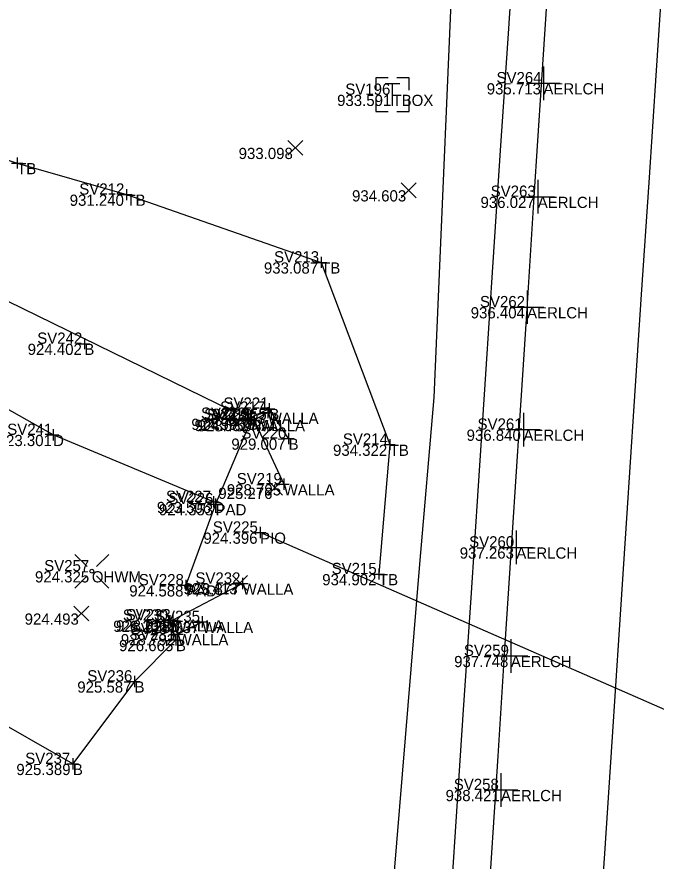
# Model space of a CAD drawing. Extents: x 1988835 to 1989144, y 657973 to 659339.
# Drawn here: x 1988936.8 to 1988993.8, y 658662.1 to 658737.4 of the extents above; entities that cross this region are included whole.
import ezdxf

# ---------------------------------------------------------------- set-up
doc = ezdxf.new("R2010")
doc.units = 0
for name, color, linetype in [('BR_X_SV_Abut', 7, 'Continuous'), ('BR_X_SV_Abut_Text', 7, 'Continuous'), ('DR_X_Culvert', 7, 'Continuous'), ('DR_X_Ditch', 7, 'Continuous'), ('DR_X_Elev_Flow', 7, 'Continuous'), ('PM_X_CL_Pass_Proh_Rt', 7, 'Continuous'), ('PV_X_EOP', 7, 'Continuous'), ('PV_X_Shoulder_Aggregate', 7, 'Continuous'), ('RD_X_Concrete_Pad', 7, 'Continuous'), ('SV_X_Break_Lines', 7, 'Continuous'), ('SV_X_Control_Cells_Found', 7, 'Continuous'), ('SV_X_LiDAR_Check_Spots', 7, 'Continuous'), ('SV_X_Random_Point', 7, 'Continuous'), ('SV_X_Shot_Marker', 7, 'Continuous'), ('SV_X_Text_Comment', 7, 'Continuous'), ('SV_X_Top_of_Bank', 7, 'Continuous'), ('UT_X_Telecom', 7, 'Continuous'), ('UT_X_Telecom_Cells', 7, 'Continuous')]:
    doc.layers.add(name, color=color, linetype=linetype)

msp = doc.modelspace()

# ---------------------------------------------------------------- linework, layer by layer
at = {"layer": 'BR_X_SV_Abut'}
for points in [[(1988959.153, 658702.097), (1988957.947, 658701.429), (1988960.579, 658695.713)], [(1988956.909, 658686.847), (1988950.685, 658683.575), (1988951.112, 658682.342), (1988953.32, 658683.43)]]:
    msp.add_lwpolyline(points, dxfattribs=at)
at = {"layer": 'DR_X_Culvert'}
msp.add_line((1989019.511, 658664.679), (1988958.476, 658691.4), dxfattribs=at)
at = {"layer": 'DR_X_Ditch'}
msp.add_lwpolyline([(1988954.33, 658694.137), (1988940.011, 658700.115), (1988927.983, 658706.906), (1988920.687, 658710.159)], dxfattribs=at)
at = {"layer": 'DR_X_Elev_Flow'}
for p, q in [((1988958.476, 658691.9), (1988958.476, 658690.9)), ((1988957.976, 658691.4), (1988958.976, 658691.4)), ((1988958.476, 658691.4), (1988958.476, 658691.4))]:
    msp.add_line(p, q, dxfattribs=at)
at = {"layer": 'PM_X_CL_Pass_Proh_Rt'}
msp.add_lwpolyline([(1988985.91, 658612.87), (1988986.569, 658622.848), (1988987.228, 658632.826), (1988987.887, 658642.804), (1988988.547, 658652.783), (1988989.206, 658662.761), (1988989.865, 658672.739), (1988990.524, 658682.717), (1988991.184, 658692.696), (1988991.843, 658702.674), (1988992.502, 658712.652), (1988993.161, 658722.63), (1988993.821, 658732.609), (1988994.48, 658742.587), (1988995.139, 658752.565), (1988995.798, 658762.543), (1988996.458, 658772.522), (1988997.117, 658782.5), (1988997.776, 658792.478), (1988998.435, 658802.456), (1988999.095, 658812.435), (1988999.754, 658822.413), (1989000.413, 658832.391), (1989001.072, 658842.369)], dxfattribs=at)
at = {"layer": 'PV_X_EOP'}
msp.add_lwpolyline([(1988990.638, 658841.098), (1988989.993, 658831.118), (1988989.347, 658821.139), (1988988.702, 658811.16), (1988988.057, 658801.181), (1988987.411, 658791.202), (1988986.766, 658781.223), (1988986.12, 658771.244), (1988985.475, 658761.264), (1988984.83, 658751.285), (1988984.184, 658741.306), (1988983.539, 658731.327), (1988982.893, 658721.348), (1988982.248, 658711.369), (1988981.602, 658701.389), (1988980.957, 658691.41), (1988980.312, 658681.431), (1988979.666, 658671.452), (1988979.021, 658661.473), (1988978.375, 658651.494), (1988977.73, 658641.515), (1988977.084, 658631.535), (1988976.439, 658621.556), (1988975.794, 658611.577)], dxfattribs=at)
at = {"layer": 'PV_X_Shoulder_Aggregate'}
msp.add_lwpolyline([(1988987.168, 658835.248), (1988986.507, 658825.269), (1988985.846, 658815.291), (1988985.185, 658805.313), (1988984.524, 658795.335), (1988983.863, 658785.357), (1988983.203, 658775.379), (1988982.542, 658765.401), (1988981.881, 658755.422), (1988981.22, 658745.444), (1988980.559, 658735.466), (1988979.898, 658725.488), (1988979.237, 658715.51), (1988978.577, 658705.532), (1988977.916, 658695.554), (1988977.255, 658685.575), (1988976.594, 658675.597), (1988975.933, 658665.619), (1988975.272, 658655.641), (1988974.612, 658645.663), (1988973.951, 658635.685), (1988973.29, 658625.707), (1988972.629, 658615.728)], dxfattribs=at)
at = {"layer": 'RD_X_Concrete_Pad'}
msp.add_lwpolyline([(1988957.682, 658701.45), (1988954.501, 658693.936), (1988951.864, 658686.696)], dxfattribs=at)
at = {"layer": 'SV_X_Break_Lines'}
for points in [[(1988961.012, 658699.789), (1988959.296, 658702.449), (1988957.403, 658701.554), (1988930.572, 658714.671)], [(1988942.8, 658708.246), (1988942.8, 658708.246)], [(1988950.438, 658683.541), (1988950.966, 658681.818), (1988947.272, 658678.12), (1988941.777, 658670.765), (1988909.757, 658689.092), (1988888.695, 658704.246)]]:
    msp.add_lwpolyline(points, dxfattribs=at)
at = {"layer": 'SV_X_Control_Cells_Found'}
for p, q in [((1988941.958, 658689.454), (1988943.051, 658688.36)), ((1988943.884, 658688.36), (1988944.976, 658689.454)), ((1988941.958, 658686.435), (1988943.051, 658687.529)), ((1988943.884, 658687.529), (1988944.976, 658686.435))]:
    msp.add_line(p, q, dxfattribs=at)
msp.add_circle((1988943.468, 658687.95), 0.17, dxfattribs=at)
at = {"layer": 'SV_X_LiDAR_Check_Spots'}
for p, q in [((1988983.736, 658732.986), (1988983.736, 658729.986)), ((1988982.236, 658731.486), (1988985.236, 658731.486)), ((1988983.736, 658731.486), (1988983.736, 658731.486)), ((1988983.233, 658722.855), (1988983.233, 658719.855)), ((1988981.733, 658721.355), (1988984.733, 658721.355)), ((1988983.233, 658721.355), (1988983.233, 658721.355)), ((1988982.286, 658713.006), (1988982.286, 658710.006)), ((1988980.786, 658711.506), (1988983.786, 658711.506)), ((1988982.286, 658711.506), (1988982.286, 658711.506)), ((1988981.953, 658702.083), (1988981.953, 658699.083)), ((1988980.453, 658700.583), (1988983.453, 658700.583)), ((1988981.953, 658700.583), (1988981.953, 658700.583)), ((1988981.325, 658691.573), (1988981.325, 658688.573)), ((1988979.825, 658690.073), (1988982.825, 658690.073)), ((1988981.325, 658690.073), (1988981.325, 658690.073)), ((1988980.837, 658681.892), (1988980.837, 658678.892)), ((1988979.337, 658680.392), (1988982.337, 658680.392)), ((1988980.837, 658680.392), (1988980.837, 658680.392)), ((1988979.955, 658669.937), (1988979.955, 658666.937)), ((1988978.455, 658668.437), (1988981.455, 658668.437)), ((1988979.955, 658668.437), (1988979.955, 658668.437))]:
    msp.add_line(p, q, dxfattribs=at)
at = {"layer": 'SV_X_Random_Point'}
for p, q in [((1988960.954, 658725.055), (1988962.287, 658726.39)), ((1988960.954, 658726.39), (1988962.287, 658725.055)), ((1988971.054, 658721.27), (1988972.387, 658722.605)), ((1988971.054, 658722.605), (1988972.387, 658721.27)), ((1988959.142, 658694.733), (1988960.475, 658696.068)), ((1988959.142, 658696.068), (1988960.475, 658694.733)), ((1988956.017, 658686.222), (1988957.35, 658687.557)), ((1988956.017, 658687.557), (1988957.35, 658686.222)), ((1988941.859, 658683.513), (1988943.192, 658684.848)), ((1988941.859, 658684.848), (1988943.192, 658683.513))]:
    msp.add_line(p, q, dxfattribs=at)
at = {"layer": 'SV_X_Shot_Marker'}
for p, q in [((1988936.302, 658724.364), (1988937.302, 658724.364)), ((1988936.802, 658724.864), (1988936.802, 658723.864)), ((1988936.802, 658724.364), (1988936.802, 658724.364)), ((1988946.553, 658722.048), (1988946.553, 658721.048)), ((1988946.053, 658721.548), (1988947.053, 658721.548)), ((1988946.553, 658721.548), (1988946.553, 658721.548)), ((1988963.916, 658716.002), (1988963.916, 658715.002)), ((1988963.416, 658715.502), (1988964.416, 658715.502)), ((1988963.916, 658715.502), (1988963.916, 658715.502)), ((1988942.8, 658708.746), (1988942.8, 658707.746)), ((1988942.3, 658708.246), (1988943.3, 658708.246)), ((1988942.8, 658708.246), (1988942.8, 658708.246)), ((1988958.796, 658702.449), (1988959.796, 658702.449)), ((1988959.153, 658702.597), (1988959.153, 658701.597)), ((1988959.296, 658702.949), (1988959.296, 658701.949)), ((1988959.296, 658702.449), (1988959.296, 658702.449)), ((1988957.403, 658702.054), (1988957.403, 658701.054)), ((1988957.682, 658701.95), (1988957.682, 658700.95)), ((1988957.947, 658701.929), (1988957.947, 658700.929)), ((1988958.653, 658702.097), (1988959.653, 658702.097)), ((1988959.153, 658702.097), (1988959.153, 658702.097)), ((1988956.903, 658701.554), (1988957.903, 658701.554)), ((1988957.182, 658701.45), (1988958.182, 658701.45)), ((1988957.403, 658701.554), (1988957.403, 658701.554)), ((1988957.447, 658701.429), (1988958.447, 658701.429)), ((1988957.682, 658701.45), (1988957.682, 658701.45)), ((1988957.947, 658701.429), (1988957.947, 658701.429)), ((1988939.511, 658700.115), (1988940.511, 658700.115)), ((1988940.011, 658700.615), (1988940.011, 658699.615)), ((1988940.011, 658700.115), (1988940.011, 658700.115)), ((1988961.012, 658700.289), (1988961.012, 658699.289)), ((1988960.512, 658699.789), (1988961.512, 658699.789)), ((1988961.012, 658699.789), (1988961.012, 658699.789)), ((1988970.033, 658699.743), (1988970.033, 658698.743)), ((1988969.533, 658699.243), (1988970.533, 658699.243)), ((1988970.033, 658699.243), (1988970.033, 658699.243)), ((1988960.079, 658695.713), (1988961.079, 658695.713)), ((1988960.579, 658696.213), (1988960.579, 658695.213)), ((1988960.579, 658695.713), (1988960.579, 658695.713)), ((1988953.83, 658694.137), (1988954.83, 658694.137)), ((1988954.33, 658694.637), (1988954.33, 658693.637)), ((1988954.33, 658694.137), (1988954.33, 658694.137)), ((1988954.501, 658694.436), (1988954.501, 658693.436)), ((1988954.001, 658693.936), (1988955.001, 658693.936)), ((1988954.501, 658693.936), (1988954.501, 658693.936)), ((1988969.072, 658688.198), (1988969.072, 658687.198)), ((1988956.909, 658687.347), (1988956.909, 658686.347)), ((1988968.572, 658687.698), (1988969.572, 658687.698)), ((1988969.072, 658687.698), (1988969.072, 658687.698)), ((1988951.364, 658686.696), (1988952.364, 658686.696)), ((1988951.864, 658687.196), (1988951.864, 658686.196)), ((1988951.864, 658686.696), (1988951.864, 658686.696)), ((1988956.409, 658686.847), (1988957.409, 658686.847)), ((1988956.909, 658686.847), (1988956.909, 658686.847)), ((1988949.938, 658683.541), (1988950.938, 658683.541)), ((1988950.185, 658683.575), (1988951.185, 658683.575)), ((1988950.438, 658684.041), (1988950.438, 658683.041)), ((1988950.438, 658683.541), (1988950.438, 658683.541)), ((1988950.685, 658684.075), (1988950.685, 658683.075)), ((1988950.685, 658683.575), (1988950.685, 658683.575)), ((1988953.32, 658683.93), (1988953.32, 658682.93)), ((1988951.112, 658682.842), (1988951.112, 658681.842)), ((1988952.82, 658683.43), (1988953.82, 658683.43)), ((1988953.32, 658683.43), (1988953.32, 658683.43)), ((1988950.612, 658682.342), (1988951.612, 658682.342)), ((1988950.966, 658682.318), (1988950.966, 658681.318)), ((1988951.112, 658682.342), (1988951.112, 658682.342)), ((1988950.466, 658681.818), (1988951.466, 658681.818)), ((1988950.966, 658681.818), (1988950.966, 658681.818)), ((1988947.272, 658678.62), (1988947.272, 658677.62)), ((1988946.772, 658678.12), (1988947.772, 658678.12)), ((1988947.272, 658678.12), (1988947.272, 658678.12)), ((1988941.277, 658670.765), (1988942.277, 658670.765)), ((1988941.777, 658671.265), (1988941.777, 658670.265)), ((1988941.777, 658670.765), (1988941.777, 658670.765))]:
    msp.add_line(p, q, dxfattribs=at)
at = {"layer": 'SV_X_Top_of_Bank'}
msp.add_lwpolyline([(1988906.592, 658735.065), (1988922.996, 658728.928), (1988936.802, 658724.364), (1988946.553, 658721.548), (1988963.916, 658715.502), (1988970.033, 658699.243), (1988969.072, 658687.698)], dxfattribs=at)
at = {"layer": 'UT_X_Telecom'}
msp.add_lwpolyline([(1988967.084, 658620.124), (1988972.731, 658688.59), (1988973.99, 658703.435), (1988975.999, 658749.743), (1988978.848, 658805.853), (1988980.812, 658827.93)], dxfattribs=at)
at = {"layer": 'UT_X_Telecom_Cells'}
for p, q in [((1988969.632, 658731.455), (1988970.932, 658731.455)), ((1988970.282, 658729.455), (1988970.282, 658731.455)), ((1988970.282, 658730.455), (1988970.282, 658730.455))]:
    msp.add_line(p, q, dxfattribs=at)
for points in [[(1988969.882, 658731.955), (1988968.782, 658731.955), (1988968.782, 658730.855)], [(1988971.782, 658730.855), (1988971.782, 658731.955), (1988970.682, 658731.955)], [(1988968.782, 658730.055), (1988968.782, 658728.955), (1988969.882, 658728.955)], [(1988970.682, 658728.955), (1988971.782, 658728.955), (1988971.782, 658730.055)]]:
    msp.add_lwpolyline(points, dxfattribs=at)

# ---------------------------------------------------------------- texts
at = {"layer": 'BR_X_SV_Abut_Text'}
for s, p in [('SV217', (1988954.904, 658702.097)), ('SV218', (1988953.741, 658701.429)), ('928.753', (1988954.103, 658701.097)), ('WALLA', (1988959.153, 658701.097)), ('928.759', (1988952.906, 658700.429)), ('WALLA', (1988957.947, 658700.429)), ('SV219', (1988956.391, 658695.713)), ('928.795', (1988955.508, 658694.713)), ('WALLA', (1988960.579, 658694.713)), ('SV232', (1988952.706, 658686.847)), ('928.877', (1988951.806, 658685.847)), ('WALLA', (1988956.909, 658685.847)), ('SV233', (1988946.489, 658683.575)), ('SV235', (1988949.102, 658683.43)), ('928.828', (1988945.625, 658682.575)), ('WALLA', (1988950.685, 658682.575)), ('SV234', (1988946.934, 658682.342)), ('928.837', (1988948.217, 658682.43)), ('WALLA', (1988953.32, 658682.43)), ('928.792', (1988946.055, 658681.342)), ('WALLA', (1988951.112, 658681.342))]:
    msp.add_text(s, height=1, dxfattribs=at).set_placement(p)
at = {"layer": 'SV_X_Text_Comment'}
for s, p in [('SV264', (1988979.558, 658731.486)), ('SV196', (1988966.072, 658730.455)), ('SV212', (1988942.35, 658721.548)), ('SV263', (1988979.037, 658721.355)), ('SV213', (1988959.721, 658715.502)), ('SV262', (1988978.083, 658711.506)), ('SV242', (1988938.597, 658708.246)), ('SV221', (1988955.209, 658702.449)), ('SV222', (1988953.2, 658701.554)), ('SV223', (1988953.486, 658701.45)), ('SV261', (1988977.867, 658700.583)), ('SV241', (1988935.924, 658700.115)), ('SV220', (1988956.805, 658699.789)), ('SV214', (1988965.855, 658699.243)), ('SV227', (1988950.081, 658694.137)), ('SV226', (1988950.291, 658693.936)), ('SV225', (1988954.259, 658691.4)), ('SV260', (1988977.118, 658690.073)), ('SV257', (1988939.219, 658687.95)), ('SV215', (1988964.854, 658687.698)), ('SV228', (1988947.659, 658686.696)), ('SV230', (1988946.23, 658683.541)), ('SV231', (1988946.879, 658681.818)), ('SV259', (1988976.65, 658680.392)), ('SV236', (1988943.062, 658678.12)), ('SV237', (1988937.527, 658670.765)), ('SV258', (1988975.749, 658668.437))]:
    msp.add_text(s, height=1, dxfattribs=at).set_placement(p)
at = {"layer": 'UT_X_Telecom'}
for s, p in [('AERLCH', (1988983.736, 658730.486)), ('TBOX', (1988970.282, 658729.455)), ('TB', (1988936.802, 658723.364)), ('TB', (1988946.553, 658720.548)), ('AERLCH', (1988983.233, 658720.355)), ('TB', (1988963.916, 658714.502)), ('AERLCH', (1988982.286, 658710.506)), ('B', (1988942.8, 658707.246)), ('B', (1988959.296, 658701.449)), ('B', (1988957.403, 658700.554)), ('PAD', (1988957.682, 658700.45)), ('D', (1988940.011, 658699.115)), ('AERLCH', (1988981.953, 658699.583)), ('B', (1988961.012, 658698.789)), ('TB', (1988970.033, 658698.243)), ('D', (1988954.33, 658693.137)), ('PAD', (1988954.501, 658692.936)), ('PIO', (1988958.476, 658690.4)), ('AERLCH', (1988981.325, 658689.073)), ('OHWM', (1988943.468, 658686.95)), ('TB', (1988969.072, 658686.698)), ('PAD', (1988951.864, 658685.696)), ('B', (1988950.438, 658682.541)), ('B', (1988950.966, 658680.818)), ('AERLCH', (1988980.837, 658679.392)), ('B', (1988947.272, 658677.12)), ('B', (1988941.777, 658669.765)), ('AERLCH', (1988979.955, 658667.437))]:
    msp.add_text(s, height=1, dxfattribs=at).set_placement(p)
at = {"layer": 'UT_X_Telecom_Cells'}
for s, p in [('935.713', (1988978.686, 658730.486)), ('933.591', (1988965.342, 658729.455)), ('933.098', (1988956.561, 658724.722)), ('934.603', (1988966.671, 658720.938)), ('931.240', (1988941.492, 658720.548)), ('936.027', (1988978.13, 658720.355)), ('933.087', (1988958.814, 658714.502)), ('936.404', (1988977.255, 658710.506)), ('924.402', (1988937.744, 658707.246)), ('927.855', (1988954.225, 658701.449)), ('924.996', (1988952.339, 658700.554)), ('924.682', (1988952.625, 658700.45)), ('923.301', (1988935.07, 658699.115)), ('936.840', (1988976.892, 658699.583)), ('929.007', (1988955.909, 658698.789)), ('934.322', (1988964.977, 658698.243)), ('925.276', (1988954.745, 658694.4)), ('923.506', (1988949.266, 658693.137)), ('924.353', (1988949.452, 658692.936)), ('924.396', (1988953.412, 658690.4)), ('937.263', (1988976.276, 658689.073)), ('924.325', (1988938.397, 658686.95)), ('934.902', (1988964.015, 658686.698)), ('924.588', (1988946.805, 658685.696)), ('925.413', (1988951.634, 658685.89)), ('924.493', (1988937.476, 658683.181)), ('926.236', (1988945.374, 658682.541)), ('926.665', (1988945.895, 658680.818)), ('937.748', (1988975.778, 658679.392)), ('925.587', (1988942.169, 658677.12)), ('925.389', (1988936.735, 658669.765)), ('938.421', (1988975.014, 658667.437))]:
    msp.add_text(s, height=1, dxfattribs=at).set_placement(p)

doc.saveas('drawing.dxf')
